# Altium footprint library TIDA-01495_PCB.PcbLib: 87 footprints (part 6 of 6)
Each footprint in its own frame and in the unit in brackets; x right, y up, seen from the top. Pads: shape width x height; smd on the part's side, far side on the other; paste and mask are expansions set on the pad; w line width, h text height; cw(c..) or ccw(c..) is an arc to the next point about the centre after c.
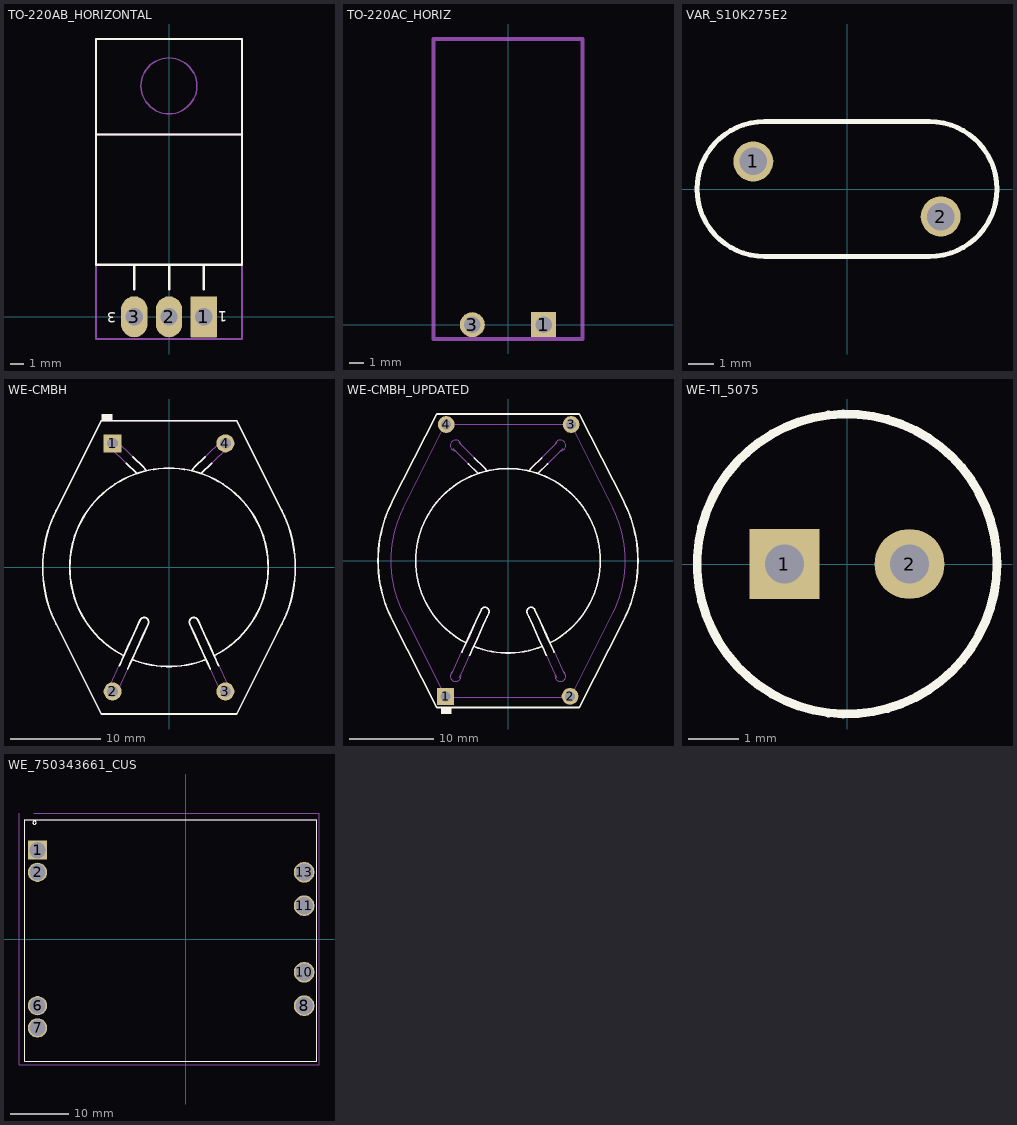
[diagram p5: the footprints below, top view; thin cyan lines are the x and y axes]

## TO-220AB_HORIZONTAL [mm] "For SolarMagic, with tab facing heatsink, away from PCB"
height 4.83
pads (3):
  rrect5% 1.93x3 hole 1.27: 1(2.54,0)
  rrect100% 1.93x3 hole 1.27: 2(0,0) 3(-2.54,0)
Top Overlay:
  lines w0.178: -5.34,13.335 5.34,13.335 ; -2.54,2 -2.54,3.8 ; 0.01,2 0.01,3.8 ; 2.54,2 2.54,3.8 ; -5.34,3.81 5.34,3.81 5.34,20.32 -5.34,20.32 -5.34,3.81
  text "1" at 4.264,0.407 h0.76
  text "3" at -3.871,0.316 h0.76
Mechanical 5:
  lines w0.1: -0.005,14.845 cw(c-0.005,16.89) -0.005,18.935 cw(c-0.005,16.89) -0.005,14.845
  lines w0.127: -5.34,13.335 5.34,13.335 ; -2.54,2 -2.54,3.8 ; 0.01,2 0.01,3.8 ; 2.54,2 2.54,3.8 ; -5.34,3.81 -5.34,20.32 5.34,20.32 5.34,3.81 ; -5.34,3.81 5.34,3.81 ; -5.34,3.81 -5.34,-1.625 5.34,-1.625 5.34,3.81
  text "3" at -3.762,0.737 h1.52
  text "1" at 4.344,0.792 h1.52
  text ".Designator" at 1.728,0.603 h1.02
3D body "to-220-leadbentup.stp": height 4.88, standoff -2.14, extent -5.335,-0.3 5.335,20.325

## TO-220AC_HORIZ [mil]
pads (2):
  rect 70x70 hole 47: 1(100,0)
  round 70 hole 47: 3(-100,0)
Mechanical 5:
  lines w10: -208.66,-40 208.66,-40 208.66,800 -208.66,800 -208.66,-40
  text ".Designator" at 50,-60.47 h40
3D body: height 180, standoff 0, extent -210,200 208.66,800

## VAR_S10K275E2 [mm] "EPCOS"
height 14.5
pads (2):
  round 1.6 hole 1.1: 1(-3.75,1.1) 2(3.75,-1.1)
Top Overlay:
  lines w0.2: -3.3,-2.7 cw(c-3.3,0) -3.3,2.7 3.3,2.7 cw(c3.3,0) 3.3,-2.7 -3.3,-2.7
Mechanical 5:
  lines w0.1: -3.3,-2.7 cw(c-3.3,0) -3.3,2.7 3.3,2.7 cw(c3.3,0) 3.3,-2.7 -3.3,-2.7
  text ".Designator" at -1.8,-0.5 h1.02
3D body: height 7, standoff -3, extent -4.172,0.676 -3.325,1.524
3D body: height 7, standoff -3, extent 3.328,-1.524 4.175,-0.676
3D body: height 14.99, standoff 3.01, extent -5.976,-2.7 5.976,2.7

## WE-CMBH [mm] "THT Inductor, 4-Leads, Body 28 x 32.5mm"
height 22
pads (4):
  rect 2x2 hole 1.2: 1(-6.25,13.75)
  round 2 hole 1.2: 2(-6.25,-13.75) 3(6.25,-13.75) 4(6.25,13.75)
Top Overlay:
  rectangle: -7.5,16.25 -6.25,17
  lines w0.2: -5.492,-10.874 -5.235,-10.308 -4.593,-8.897 -3.848,-7.258 -3.207,-5.847 cw(c-2.752,-6.054) -2.375,-5.725 cw(c-2.752,-6.054) -2.297,-6.261 -2.938,-7.672 -3.683,-9.311 -4.324,-10.722 -4.582,-11.288 ; -4.993,-9.801 cw(c0,0) 4.993,-9.801 ; -4.716,11.547 -3.556,10.409 ; -4.083,-10.214 ccw(c0,0) 4.094,-10.21 ; -4.016,12.261 -2.806,11.075 cw(c-4.206,9.646) -2.512,10.709 ; -2.5,-6.752 -2.5,-6.708 ; 2.5,-6.752 2.5,-6.708 ; 2.512,10.709 cw(c4.206,9.646) 2.806,11.075 4.016,12.261 ; 3.556,10.409 4.716,11.547 ; 4.582,-11.288 4.324,-10.722 3.683,-9.311 2.938,-7.672 2.297,-6.261 cw(c2.752,-6.054) 2.375,-5.725 cw(c2.752,-6.054) 3.207,-5.847 3.848,-7.258 4.593,-8.897 5.235,-10.308 5.492,-10.874 ; -7.5,16.25 7.5,16.25 ; -7.5,16.25 7.5,16.25 ; -7.5,16.25 -12.508,6.289 ccw(c0,0) -12.508,-6.289 -7.5,-16.25 7.5,-16.25 12,-7.25 12.508,-6.289 ccw(c0,0) 12.508,6.289 7.5,16.25
Mechanical 5:
  lines w0.1: -4.993,-9.801 cw(c0,0) 4.993,-9.801 ; -4.083,-10.214 ccw(c0,0) 4.094,-10.21
  lines w0.127: -12.516,-6.272 -7.508,-16.234 ; -12.508,-6.289 cw(c0,0) -12.508,6.289 -7.5,16.25 7.5,16.25 12.508,6.289 cw(c0,0) 12.508,-6.289 7.5,-16.25 -7.5,-16.25 ; -6.705,-13.542 -6.448,-12.977 -5.492,-10.874 -5.235,-10.308 -4.593,-8.897 -3.848,-7.258 -3.207,-5.847 cw(c-2.752,-6.054) -2.375,-5.725 cw(c-2.752,-6.054) -2.297,-6.261 -2.938,-7.672 -3.683,-9.311 -4.324,-10.722 -4.582,-11.288 -5.537,-13.391 -5.794,-13.956 ; -6.599,13.392 -4.716,11.547 -3.556,10.409 ; -6.533,-13.165 ccw(c-6.25,-13.75) -6.25,-14.4 ccw(c-6.25,-13.75) -5.623,-13.579 ; -6.303,13.102 cw(c-6.25,13.75) -5.603,13.816 ; -5.899,14.107 -4.016,12.261 -2.806,11.075 cw(c-4.206,9.646) -2.512,10.709 ; -2.5,-6.752 -2.5,-6.708 ; 2.5,-6.752 2.5,-6.708 ; 2.512,10.709 cw(c4.206,9.646) 2.806,11.075 4.016,12.261 5.899,14.107 ; 3.556,10.409 4.716,11.547 6.599,13.392 ; 5.603,13.816 cw(c6.25,13.75) 6.303,13.102 ; 5.623,-13.579 ccw(c6.25,-13.75) 6.25,-14.4 ccw(c6.25,-13.75) 6.533,-13.165 ; 5.794,-13.956 5.537,-13.391 4.582,-11.288 4.324,-10.722 3.683,-9.311 2.938,-7.672 2.297,-6.261 cw(c2.752,-6.054) 2.375,-5.725 cw(c2.752,-6.054) 3.207,-5.847 3.848,-7.258 4.593,-8.897 5.235,-10.308 5.492,-10.874 6.448,-12.977 6.705,-13.542
  text ".Designator" at -0.375,-0.712 h1.02
3D body "WE-CMBH.stp": height 20, standoff -3, extent -13.831,-16.25 13.832,16.25

## WE-CMBH_UPDATED [mm] "THT Inductor, 4-Leads, Body 28 x 32.5mm"
height 22
pads (4):
  rect 2x2 hole 1.2: 1(-7.45,-16.175)
  round 2 hole 1.2: 2(7.4,-16.175) 3(7.525,16.25) 4(-7.375,16.25)
Top Overlay:
  rectangle: -7.981,-18.276 -6.731,-17.526
  lines w0.2: -13.848,-6.962 cw(c0,0) -13.848,6.962 ; -13.843,6.985 -8.484,17.475 ; -13.792,-7.061 -8.484,-17.501 ; -8.458,17.501 7.5,17.5 ; -8.453,-17.5 8.458,-17.501 ; -7.551,17.5 8.458,17.501 ; -5.492,-10.874 -5.235,-10.308 -4.593,-8.897 -3.848,-7.258 -3.207,-5.847 cw(c-2.752,-6.054) -2.375,-5.725 cw(c-2.752,-6.054) -2.297,-6.261 -2.938,-7.672 -3.683,-9.311 -4.324,-10.722 -4.582,-11.288 ; -4.993,-9.801 cw(c0,0) 4.993,-9.801 ; -4.716,11.547 -3.556,10.409 ; -4.083,-10.214 ccw(c0,0) 4.094,-10.21 ; -4.016,12.261 -2.806,11.075 cw(c-4.206,9.646) -2.512,10.709 ; -2.5,-6.752 -2.5,-6.708 ; 2.5,-6.752 2.5,-6.708 ; 2.512,10.709 cw(c4.206,9.646) 2.806,11.075 4.016,12.261 ; 3.556,10.409 4.716,11.547 ; 4.582,-11.288 4.324,-10.722 3.683,-9.311 2.938,-7.672 2.297,-6.261 cw(c2.752,-6.054) 2.375,-5.725 cw(c2.752,-6.054) 3.207,-5.847 3.848,-7.258 4.593,-8.897 5.235,-10.308 5.492,-10.874 ; 8.484,-17.501 13.792,-7.061 ; 8.484,17.475 13.843,6.985 ; 13.848,-6.962 ccw(c0,0) 13.848,6.962
Mechanical 5:
  lines w0.1: -4.993,-9.801 cw(c0,0) 4.993,-9.801 ; -4.083,-10.214 ccw(c0,0) 4.094,-10.21
  lines w0.127: -12.516,-6.272 -7.508,-16.234 ; -12.508,-6.289 cw(c0,0) -12.508,6.289 -7.5,16.25 7.5,16.25 12.508,6.289 cw(c0,0) 12.508,-6.289 7.5,-16.25 -7.5,-16.25 ; -6.705,-13.542 -6.448,-12.977 -5.492,-10.874 -5.235,-10.308 -4.593,-8.897 -3.848,-7.258 -3.207,-5.847 cw(c-2.752,-6.054) -2.375,-5.725 cw(c-2.752,-6.054) -2.297,-6.261 -2.938,-7.672 -3.683,-9.311 -4.324,-10.722 -4.582,-11.288 -5.537,-13.391 -5.794,-13.956 ; -6.599,13.392 -4.716,11.547 -3.556,10.409 ; -6.533,-13.165 ccw(c-6.25,-13.75) -6.25,-14.4 ccw(c-6.25,-13.75) -5.623,-13.579 ; -6.303,13.102 cw(c-6.25,13.75) -5.603,13.816 ; -5.899,14.107 -4.016,12.261 -2.806,11.075 cw(c-4.206,9.646) -2.512,10.709 ; -2.5,-6.752 -2.5,-6.708 ; 2.5,-6.752 2.5,-6.708 ; 2.512,10.709 cw(c4.206,9.646) 2.806,11.075 4.016,12.261 5.899,14.107 ; 3.556,10.409 4.716,11.547 6.599,13.392 ; 5.603,13.816 cw(c6.25,13.75) 6.303,13.102 ; 5.623,-13.579 ccw(c6.25,-13.75) 6.25,-14.4 ccw(c6.25,-13.75) 6.533,-13.165 ; 5.794,-13.956 5.537,-13.391 4.582,-11.288 4.324,-10.722 3.683,-9.311 2.938,-7.672 2.297,-6.261 cw(c2.752,-6.054) 2.375,-5.725 cw(c2.752,-6.054) 3.207,-5.847 3.848,-7.258 4.593,-8.897 5.235,-10.308 5.492,-10.874 6.448,-12.977 6.705,-13.542
  text ".Designator" at -1.5,-0.75 h1.02
3D body "WE-CMBH.stp": height 20, standoff -3, extent -13.831,-16.25 13.832,16.25

## WE-TI_5075 [mm] "Wurth WE-TI 5075"
height 8.5
pads (2):
  rect 1.4x1.4 hole 0.787: 1(-1.25,0)
  round 1.4 hole 0.787: 2(1.25,0)
Top Overlay:
  circle w0.177: c0,0 r3
Mechanical 5:
  circle w0.1: c0,0 r3
  text ".Designator" at -0.567,0.802 h1.02
3D body: height 8.5, standoff 0, extent -2.999,-2.999 2.999,2.999

## WE_750343661_CUS [mil] "TRANSFORMER, TH, 14-PIN"
height 629.92
pads (8):
  rect 130x130 hole 110.24: 1(-1000,600)
  round 130 hole 110.24: 2(-1000,450) 6(-1000,-450) 7(-1000,-600)
  round 140 hole 118.11: 8(800,-450) 10(800,-225) 11(800,225) 13(800,450)
Top Overlay:
  circle w7: c-1020,785 r11
  lines w7: -1085,-825 -1085,804.92 883.5,804.92 883.5,-825 -1085,-825
Mechanical 5:
  circle w5: c-1000,600 r19.68
  lines w5: -1085,-825 -1085,805 885,805 885,-825 -1085,-825
  text ".Designator" at -56.94,-0.65 h30
Mechanical 15:
  lines w1.97: -1125,850 -1125,-850 900,-850 900,850 -1025,850
Mechanical 17:
  text "LEAD LENGTH MAX: 4:00 MM" at -475,380 h39.37
3D body: height 598.43, standoff 0, extent -1085,-825 885,805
